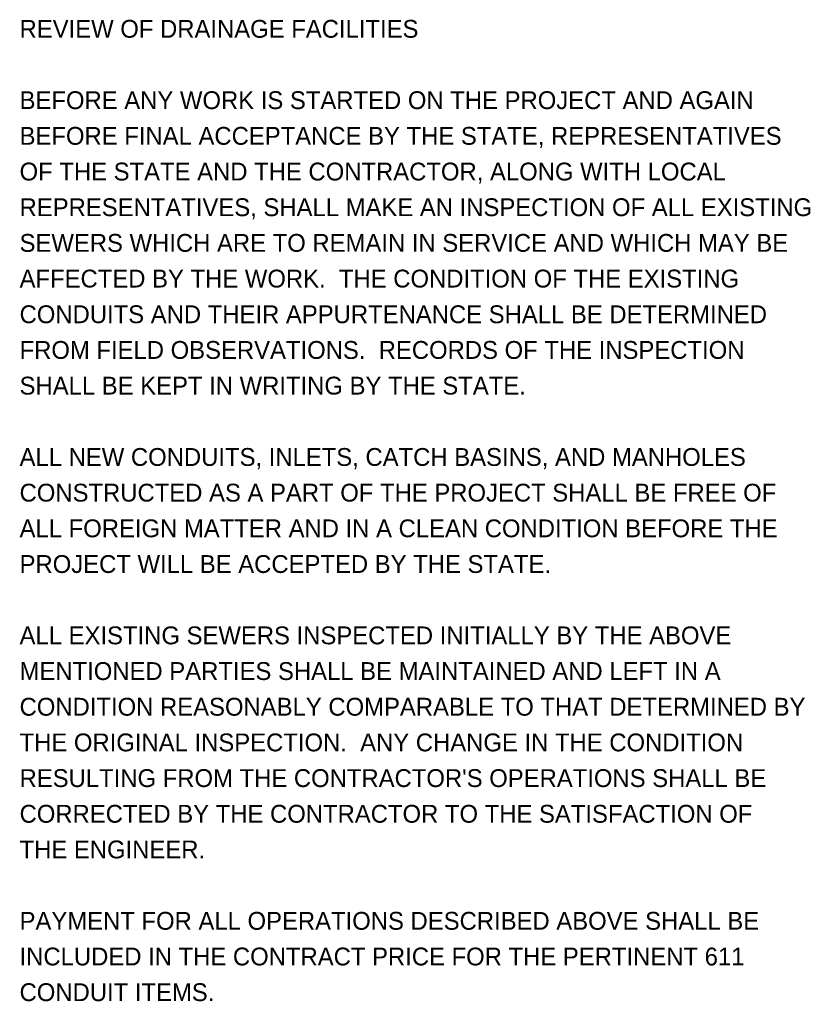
# Model space of a CAD drawing. Extents: x 0 to 58.9, y -9.9 to 22.
# Drawn here: x 38.51 to 44.71, y 13.44 to 21.14 of the extents above; entities that cross this region are included whole.
import ezdxf

# ---------------------------------------------------------------- set-up
doc = ezdxf.new("R2010")
doc.units = 0
doc.layers.add('SH_Text', color=7, linetype='Continuous')

msp = doc.modelspace()

# ---------------------------------------------------------------- texts
at = {"layer": 'SH_Text'}
for s, p in [('REVIEW OF DRAINAGE FACILITIES', (38.5064, 21)), ('BEFORE ANY WORK IS STARTED ON THE PROJECT AND AGAIN', (38.5064, 20.44)), ('BEFORE FINAL ACCEPTANCE BY THE STATE, REPRESENTATIVES', (38.5064, 20.16)), ('OF THE STATE AND THE CONTRACTOR, ALONG WITH LOCAL', (38.5064, 19.88)), ('REPRESENTATIVES, SHALL MAKE AN INSPECTION OF ALL EXISTING', (38.5064, 19.6)), ('SEWERS WHICH ARE TO REMAIN IN SERVICE AND WHICH MAY BE', (38.5064, 19.32)), ('AFFECTED BY THE WORK.  THE CONDITION OF THE EXISTING', (38.5064, 19.04)), ('CONDUITS AND THEIR APPURTENANCE SHALL BE DETERMINED', (38.5064, 18.76)), ('FROM FIELD OBSERVATIONS.  RECORDS OF THE INSPECTION', (38.5064, 18.48)), ('SHALL BE KEPT IN WRITING BY THE STATE.', (38.5064, 18.2)), ('ALL NEW CONDUITS, INLETS, CATCH BASINS, AND MANHOLES', (38.5064, 17.64)), ('CONSTRUCTED AS A PART OF THE PROJECT SHALL BE FREE OF', (38.5064, 17.36)), ('ALL FOREIGN MATTER AND IN A CLEAN CONDITION BEFORE THE', (38.5064, 17.08)), ('PROJECT WILL BE ACCEPTED BY THE STATE.', (38.5064, 16.8)), ('ALL EXISTING SEWERS INSPECTED INITIALLY BY THE ABOVE', (38.5064, 16.24)), ('MENTIONED PARTIES SHALL BE MAINTAINED AND LEFT IN A', (38.5064, 15.96)), ('CONDITION REASONABLY COMPARABLE TO THAT DETERMINED BY', (38.5064, 15.68)), ('THE ORIGINAL INSPECTION.  ANY CHANGE IN THE CONDITION', (38.5064, 15.4)), ("RESULTING FROM THE CONTRACTOR'S OPERATIONS SHALL BE", (38.5064, 15.12)), ('CORRECTED BY THE CONTRACTOR TO THE SATISFACTION OF', (38.5064, 14.84)), ('THE ENGINEER.', (38.5064, 14.56)), ('PAYMENT FOR ALL OPERATIONS DESCRIBED ABOVE SHALL BE', (38.5064, 14)), ('INCLUDED IN THE CONTRACT PRICE FOR THE PERTINENT 611', (38.5064, 13.72)), ('CONDUIT ITEMS.', (38.5064, 13.44))]:
    msp.add_text(s, height=0.14, dxfattribs=at).set_placement(p)

doc.saveas('drawing.dxf')
